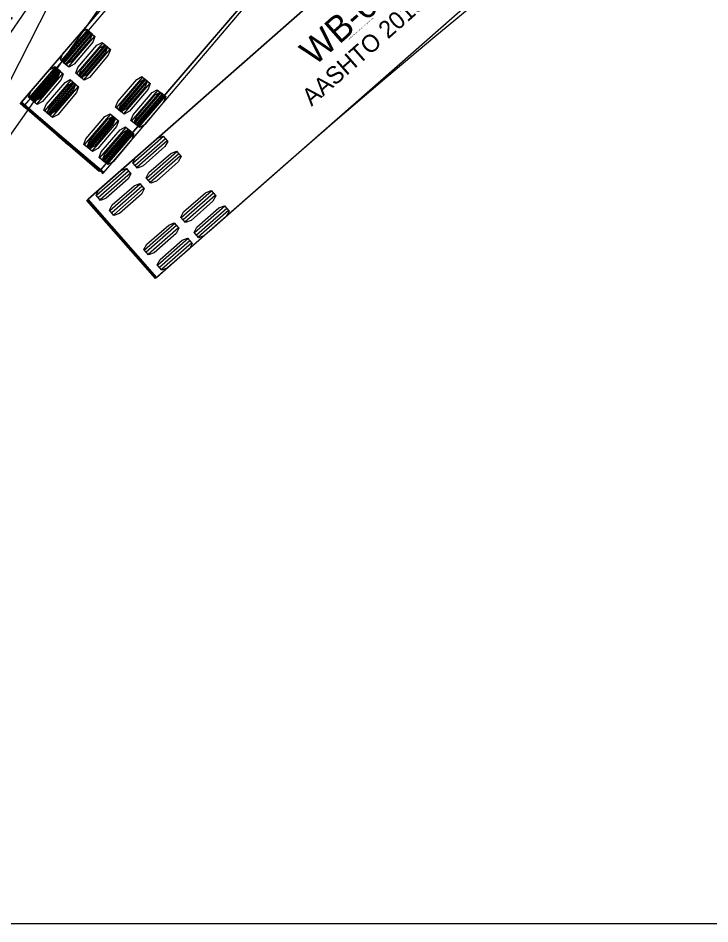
# Model space of a CAD drawing. Extents: x 973688 to 979179, y 703586 to 707602.
# Drawn here: x 976493.2 to 976549.8, y 705362.7 to 705436.7 of the extents above; entities that cross this region are included whole.
import ezdxf

# ---------------------------------------------------------------- set-up
doc = ezdxf.new("R2010")
doc.units = 0
for name, color, linetype in [('EB Right', 7, 'Continuous'), ('NB Left', 7, 'Continuous'), ('NB Right', 7, 'Continuous'), ('NO PLOT', 7, 'Continuous')]:
    doc.layers.add(name, color=color, linetype=linetype)

msp = doc.modelspace()

# ---------------------------------------------------------------- linework, layer by layer
at = {"layer": 'EB Right'}
msp.add_line((976511.032, 705462.319), (976470.818, 705403.835), dxfattribs=at)
for points in [[(976500.751, 705466.316), (976500.732, 705466.326), (976500.7, 705466.263), (976498.128, 705461.213), (976476.718, 705419.158), (976480.505, 705417.23), (976484.292, 705415.302), (976505.703, 705457.357), (976508.274, 705462.407), (976508.306, 705462.47), (976508.286, 705462.48)], [(976514.638, 705458.597), (976490.06, 705423.558), (976484.292, 705415.302), (976483.893, 705415.505), (976483.561, 705415.308), (976471.848, 705398.273), (976465.256, 705402.805), (976477.342, 705420.384), (976499.937, 705464.787)]]:
    msp.add_lwpolyline(points, dxfattribs=at)
at = {"layer": 'NB Left'}
for p, q in [((976498.904, 705435.751), (976496.755, 705433.247)), ((976499.078, 705435.601), (976496.929, 705433.097)), ((976499.128, 705435.534), (976496.992, 705433.019)), ((976499.252, 705435.452), (976497.103, 705432.948)), ((976499.303, 705435.386), (976497.166, 705432.871)), ((976499.478, 705435.237), (976497.341, 705432.722)), ((976500.156, 705434.676), (976498.007, 705432.172)), ((976500.33, 705434.527), (976498.181, 705432.023)), ((976500.386, 705434.466), (976498.249, 705431.951)), ((976500.504, 705434.377), (976498.355, 705431.873)), ((976500.561, 705434.317), (976498.424, 705431.803)), ((976500.735, 705434.169), (976498.599, 705431.654)), ((976496.299, 705432.715), (976494.15, 705430.211)), ((976496.473, 705432.566), (976494.323, 705430.062)), ((976496.539, 705432.486), (976494.402, 705429.971)), ((976496.647, 705432.417), (976494.497, 705429.913)), ((976496.713, 705432.337), (976494.577, 705429.822)), ((976496.888, 705432.189), (976494.751, 705429.674)), ((976503.406, 705431.886), (976501.257, 705429.382)), ((976497.551, 705431.641), (976495.402, 705429.137)), ((976497.725, 705431.491), (976495.576, 705428.987)), ((976497.796, 705431.417), (976495.66, 705428.902)), ((976497.899, 705431.342), (976495.749, 705428.838)), ((976497.971, 705431.269), (976495.834, 705428.754)), ((976498.145, 705431.121), (976496.009, 705428.606)), ((976503.58, 705431.737), (976501.431, 705429.233)), ((976503.65, 705431.693), (976501.514, 705429.178)), ((976503.754, 705431.588), (976501.605, 705429.084)), ((976503.825, 705431.544), (976501.688, 705429.029)), ((976504, 705431.396), (976501.863, 705428.881)), ((976504.658, 705430.812), (976502.509, 705428.308)), ((976504.832, 705430.662), (976502.683, 705428.158)), ((976504.908, 705430.624), (976502.771, 705428.109)), ((976505.006, 705430.513), (976502.857, 705428.009)), ((976505.082, 705430.476), (976502.946, 705427.961)), ((976499.964, 705424.287), (976493.514, 705429.823)), ((976505.257, 705430.328), (976503.12, 705427.813)), ((976500.246, 705424.076), (976493.768, 705429.579)), ((976500.801, 705428.851), (976498.652, 705426.347)), ((976500.975, 705428.702), (976498.826, 705426.198)), ((976501.06, 705428.644), (976498.924, 705426.129)), ((976501.149, 705428.552), (976499, 705426.048)), ((976501.235, 705428.496), (976499.099, 705425.981)), ((976501.41, 705428.347), (976499.273, 705425.832)), ((976502.053, 705427.776), (976499.904, 705425.272)), ((976502.227, 705427.627), (976500.078, 705425.123)), ((976502.318, 705427.576), (976500.181, 705425.061)), ((976502.401, 705427.478), (976500.252, 705424.974)), ((976502.493, 705427.428), (976500.356, 705424.913)), ((976496.491, 705427.174), (976496.29, 705427.347)), ((976496.759, 705426.945), (976496.557, 705427.117)), ((976496.693, 705427.001), (976496.739, 705427.055)), ((976497.096, 705426.655), (976496.895, 705426.828)), ((976496.962, 705426.773), (976497.007, 705426.827)), ((976502.667, 705427.279), (976500.531, 705424.764)), ((976497.367, 705426.43), (976497.164, 705426.602))]:
    msp.add_line(p, q, dxfattribs=at)
for points in [[(976597.405, 705538.82), (976596.514, 705537.482), (976595.572, 705536.185), (976594.585, 705534.932), (976587.989, 705527.228), (976586.467, 705525.264), (976584.967, 705523.4), (976583.486, 705521.619), (976499.872, 705424.179), (976493.422, 705429.715), (976493.503, 705429.81), (976493.503, 705429.81)], [(976493.503, 705429.81), (976548.212, 705493.558)], [(976499.901, 705424.248), (976499.917, 705424.234), (976499.963, 705424.287), (976503.655, 705428.587), (976534.391, 705464.397), (976531.166, 705467.165), (976527.941, 705469.933), (976497.205, 705434.123), (976493.515, 705429.822), (976493.469, 705429.769), (976493.485, 705429.754)], [(976500.184, 705424.036), (976500.2, 705424.022), (976500.246, 705424.076), (976503.916, 705428.395), (976534.47, 705464.36), (976531.231, 705467.111), (976527.992, 705469.863), (976497.438, 705433.898), (976493.769, 705429.578), (976493.723, 705429.525), (976493.74, 705429.511)], [(976493.503, 705429.739), (976493.504, 705429.738), (976496.263, 705427.37), (976496.29, 705427.347), (976496.244, 705427.294), (976496.245, 705427.293), (976496.448, 705427.119)], [(976493.758, 705429.495), (976493.759, 705429.494), (976496.53, 705427.141), (976496.557, 705427.117), (976496.511, 705427.064), (976496.512, 705427.063), (976496.716, 705426.89)], [(976496.497, 705427.17), (976496.892, 705426.83)], [(976496.764, 705426.941), (976497.162, 705426.604)], [(976496.847, 705426.776), (976497.049, 705426.602), (976497.051, 705426.602), (976497.096, 705426.655), (976497.123, 705426.632), (976499.882, 705424.264), (976499.883, 705424.263)], [(976497.116, 705426.55), (976497.32, 705426.377), (976497.321, 705426.376), (976497.366, 705426.429), (976497.394, 705426.406), (976500.164, 705424.053), (976500.165, 705424.052)]]:
    msp.add_lwpolyline(points, dxfattribs=at)
for points in [[(976498.861, 705435.788), (976499.295, 705435.415), (976499.125, 705434.952), (976497.577, 705433.149), (976497.146, 705432.911), (976496.712, 705433.284), (976496.882, 705433.746), (976498.429, 705435.549)], [(976499.085, 705435.571), (976499.521, 705435.201), (976499.353, 705434.737), (976497.815, 705432.926), (976497.384, 705432.686), (976496.949, 705433.056), (976497.116, 705433.52), (976498.655, 705435.33)], [(976500.113, 705434.713), (976500.547, 705434.34), (976500.377, 705433.878), (976498.829, 705432.075), (976498.398, 705431.836), (976497.964, 705432.209), (976498.134, 705432.672), (976499.681, 705434.475)], [(976500.343, 705434.503), (976500.779, 705434.132), (976500.611, 705433.669), (976499.072, 705431.858), (976498.642, 705431.617), (976498.206, 705431.988), (976498.374, 705432.451), (976499.912, 705434.262)], [(976496.256, 705432.752), (976496.69, 705432.38), (976496.52, 705431.917), (976494.972, 705430.114), (976494.54, 705429.876), (976494.106, 705430.248), (976494.277, 705430.711), (976495.824, 705432.514)], [(976496.495, 705432.523), (976496.931, 705432.152), (976496.763, 705431.689), (976495.225, 705429.878), (976494.795, 705429.637), (976494.359, 705430.008), (976494.526, 705430.471), (976496.065, 705432.282)], [(976503.363, 705431.923), (976503.797, 705431.551), (976503.627, 705431.088), (976502.08, 705429.285), (976501.648, 705429.047), (976501.214, 705429.419), (976501.384, 705429.882), (976502.932, 705431.685)], [(976497.508, 705431.678), (976497.942, 705431.305), (976497.772, 705430.842), (976496.224, 705429.039), (976495.793, 705428.801), (976495.359, 705429.174), (976495.529, 705429.636), (976497.076, 705431.439)], [(976497.753, 705431.454), (976498.189, 705431.084), (976498.021, 705430.62), (976496.483, 705428.809), (976496.052, 705428.569), (976495.616, 705428.939), (976495.784, 705429.403), (976497.322, 705431.214)], [(976503.607, 705431.729), (976504.043, 705431.359), (976503.875, 705430.895), (976502.337, 705429.085), (976501.906, 705428.844), (976501.47, 705429.214), (976501.638, 705429.678), (976503.176, 705431.489)], [(976504.615, 705430.849), (976505.049, 705430.476), (976504.879, 705430.013), (976503.332, 705428.21), (976502.9, 705427.972), (976502.466, 705428.345), (976502.636, 705428.807), (976504.184, 705430.61)], [(976504.864, 705430.661), (976505.3, 705430.291), (976505.133, 705429.827), (976503.594, 705428.016), (976503.164, 705427.776), (976502.728, 705428.146), (976502.896, 705428.61), (976504.434, 705430.421)], [(976500.758, 705428.888), (976501.192, 705428.515), (976501.022, 705428.053), (976499.475, 705426.25), (976499.043, 705426.011), (976498.609, 705426.384), (976498.779, 705426.847), (976500.326, 705428.65)], [(976501.017, 705428.681), (976501.453, 705428.311), (976501.285, 705427.847), (976499.747, 705426.036), (976499.316, 705425.796), (976498.881, 705426.166), (976499.048, 705426.63), (976500.587, 705428.44)], [(976502.01, 705427.813), (976502.444, 705427.441), (976502.274, 705426.978), (976500.727, 705425.175), (976500.295, 705424.937), (976499.861, 705425.309), (976500.031, 705425.772), (976501.578, 705427.575)], [(976502.275, 705427.613), (976502.711, 705427.242), (976502.543, 705426.779), (976501.004, 705424.968), (976500.574, 705424.727), (976500.138, 705425.098), (976500.306, 705425.561), (976501.844, 705427.372)]]:
    msp.add_lwpolyline(points, close=True, dxfattribs=at)
for centre in [(976493.472, 705429.721), (976493.727, 705429.477), (976499.87, 705424.229), (976500.152, 705424.018)]:
    msp.add_circle(centre, 0.0266, dxfattribs=at)
for centre, radius, start, end in [((976493.472, 705429.721), 0.0363, 68.43799, 29.59933), ((976493.727, 705429.477), 0.0363, 68.72784, 29.88919), ((976496.47, 705427.146), 0.0353, 52.69672, 231.04637), ((976496.471, 705427.145), 0.0352, 229.38581, 48.38622), ((976496.738, 705426.917), 0.0353, 52.98658, 231.33623), ((976496.738, 705426.917), 0.0352, 229.67566, 48.67607), ((976496.87, 705426.803), 0.0352, 50.33486, 229.33527), ((976496.87, 705426.803), 0.0354, 233.65208, 45.83754), ((976497.139, 705426.576), 0.0352, 50.62472, 229.62513), ((976497.14, 705426.576), 0.0354, 233.94193, 46.1274), ((976498.584, 705422.713), 2.022, 49.36054, 50.0443), ((976498.875, 705422.495), 2.022, 49.6504, 50.33416)]:
    msp.add_arc(centre, radius, start, end, dxfattribs=at)
at = {"layer": 'NB Right'}
for p, q in [((976505.129, 705427.019), (976502.65, 705424.84)), ((976505.28, 705426.847), (976502.802, 705424.668)), ((976505.431, 705426.675), (976502.953, 705424.496)), ((976506.218, 705425.78), (976503.74, 705423.601)), ((976506.369, 705425.608), (976503.891, 705423.429)), ((976506.521, 705425.436), (976504.043, 705423.257)), ((976502.125, 705424.378), (976499.647, 705422.199)), ((976502.276, 705424.206), (976499.798, 705422.027)), ((976502.427, 705424.034), (976499.949, 705421.854)), ((976503.214, 705423.139), (976500.736, 705420.96)), ((976503.366, 705422.967), (976500.888, 705420.787)), ((976503.517, 705422.795), (976501.039, 705420.615)), ((976509.047, 705422.564), (976506.569, 705420.384)), ((976509.198, 705422.391), (976506.72, 705420.212)), ((976504.576, 705415.52), (976498.963, 705421.903)), ((976509.349, 705422.219), (976506.871, 705420.04)), ((976510.136, 705421.324), (976507.658, 705419.145)), ((976510.288, 705421.152), (976507.809, 705418.973)), ((976510.439, 705420.98), (976507.961, 705418.801)), ((976506.043, 705419.922), (976503.565, 705417.743)), ((976506.194, 705419.75), (976503.716, 705417.571)), ((976506.346, 705419.578), (976503.867, 705417.399)), ((976501.541, 705418.864), (976501.366, 705419.063)), ((976501.716, 705418.664), (976501.769, 705418.711)), ((976507.132, 705418.683), (976504.654, 705416.504)), ((976502.067, 705418.266), (976501.892, 705418.465)), ((976507.284, 705418.511), (976504.806, 705416.332)), ((976507.435, 705418.339), (976504.957, 705416.16))]:
    msp.add_line(p, q, dxfattribs=at)
for points in [[(976498.963, 705421.903), (976539.356, 705457.419)], [(976504.508, 705415.49), (976504.522, 705415.474), (976504.575, 705415.52), (976508.832, 705419.262), (976544.271, 705450.425), (976541.464, 705453.617), (976538.658, 705456.808), (976503.219, 705425.645), (976498.963, 705421.902), (976498.91, 705421.855), (976498.925, 705421.839)], [(976531.184, 705438.408), (976527.28, 705435.18), (976523.36, 705431.875), (976519.344, 705428.437), (976515.341, 705424.965), (976504.47, 705415.426), (976498.857, 705421.809), (976498.963, 705421.903), (976498.963, 705421.903)], [(976498.941, 705421.821), (976498.941, 705421.82), (976501.342, 705419.09), (976501.366, 705419.063), (976501.313, 705419.017), (976501.314, 705419.016), (976501.49, 705418.815)], [(976501.546, 705418.859), (976501.89, 705418.467)], [(976501.837, 705418.421), (976502.013, 705418.22), (976502.015, 705418.219), (976502.067, 705418.265), (976502.091, 705418.239), (976504.492, 705415.509), (976504.492, 705415.508)]]:
    msp.add_lwpolyline(points, dxfattribs=at)
for points in [[(976505.091, 705427.062), (976505.469, 705426.632), (976505.236, 705426.198), (976503.451, 705424.629), (976502.991, 705424.453), (976502.613, 705424.883), (976502.846, 705425.317), (976504.63, 705426.886)], [(976506.181, 705425.823), (976506.558, 705425.393), (976506.325, 705424.959), (976504.541, 705423.39), (976504.08, 705423.214), (976503.702, 705423.644), (976503.936, 705424.078), (976505.72, 705425.647)], [(976502.087, 705424.42), (976502.465, 705423.991), (976502.232, 705423.556), (976500.448, 705421.987), (976499.987, 705421.812), (976499.609, 705422.241), (976499.842, 705422.676), (976501.626, 705424.245)], [(976503.177, 705423.181), (976503.555, 705422.752), (976503.321, 705422.317), (976501.537, 705420.748), (976501.076, 705420.573), (976500.699, 705421.002), (976500.932, 705421.437), (976502.716, 705423.006)], [(976509.009, 705422.606), (976509.387, 705422.177), (976509.154, 705421.742), (976507.369, 705420.173), (976506.909, 705419.998), (976506.531, 705420.427), (976506.764, 705420.862), (976508.548, 705422.431)], [(976510.099, 705421.367), (976510.476, 705420.938), (976510.243, 705420.503), (976508.459, 705418.934), (976507.998, 705418.758), (976507.621, 705419.188), (976507.854, 705419.622), (976509.638, 705421.191)], [(976506.005, 705419.965), (976506.383, 705419.535), (976506.15, 705419.101), (976504.366, 705417.532), (976503.905, 705417.356), (976503.527, 705417.786), (976503.76, 705418.22), (976505.545, 705419.789)], [(976507.095, 705418.726), (976507.473, 705418.296), (976507.239, 705417.862), (976505.455, 705416.293), (976504.994, 705416.117), (976504.617, 705416.547), (976504.85, 705416.981), (976506.634, 705418.55)]]:
    msp.add_lwpolyline(points, close=True, dxfattribs=at)
for centre in [(976498.907, 705421.808), (976504.475, 705415.476)]:
    msp.add_circle(centre, 0.0266, dxfattribs=at)
for centre, radius, start, end in [((976498.907, 705421.808), 0.0363, 60.40435, 21.5657), ((976501.516, 705418.839), 0.0353, 44.66308, 223.01273), ((976501.516, 705418.839), 0.0352, 221.35217, 40.35258), ((976501.864, 705418.444), 0.0352, 42.30123, 221.30163), ((976501.864, 705418.443), 0.0354, 225.61844, 37.8039), ((976502.99, 705414.155), 2.022, 41.3269, 42.01066)]:
    msp.add_arc(centre, radius, start, end, dxfattribs=at)
at = {"layer": 'NO PLOT'}
msp.add_lwpolyline([(976318.336, 705802.708), (976998.336, 705802.708), (976998.336, 705362.708), (976318.336, 705362.708)], close=True, dxfattribs=at)

# ---------------------------------------------------------------- texts
at = {"layer": 'EB Right'}
msp.add_text('AASHTO 2018 (US)', height=1.41667, rotation=63.01894, dxfattribs=at).set_placement((976490.95, 705433.047))
at = {"layer": 'NB Right'}
for s, height, p in [('AASHTO 2018 (US)', 1.41667, (976517.215, 705429.454)), ('WB-67', 2.125, (976517.462, 705432.737)), ('(c) 2020 Transoft Solutions, Inc. All rights reserved.', 0.085, (976520.285, 705434.936))]:
    msp.add_text(s, height=height, rotation=41.3269, dxfattribs=at).set_placement(p)

doc.saveas('drawing.dxf')
